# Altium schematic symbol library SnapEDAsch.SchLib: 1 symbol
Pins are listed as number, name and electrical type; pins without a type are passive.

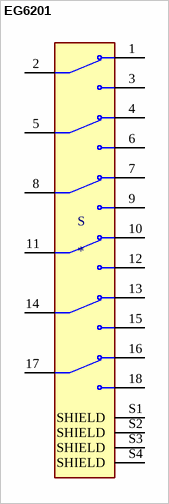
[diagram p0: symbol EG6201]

## EG6201
designator S
Slide Switch 6PDT Through Hole, Right Angle; MF: E-Switch; MP: EG6201
footprint SW_EG6201
pins: 1 NC1, 2 COM1, 3 NO1, 4 NC2, 5 COM2, 6 NO2, 7 NC3, 8 COM3, 9 NO3, 10 NC4, 11 COM4, 12 NO4, 13 NC5, 14 COM5, 15 NO5, 16 NC6, 17 COM6, 18 NO6, S1 SHIELD, S2 SHIELD, S3 SHIELD, S4 SHIELD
